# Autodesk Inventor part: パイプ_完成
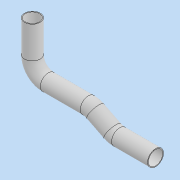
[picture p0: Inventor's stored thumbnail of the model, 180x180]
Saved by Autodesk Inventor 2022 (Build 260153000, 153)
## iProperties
Created: 2021-07
Part Number: パイプ_完成
Material: 一般
Document SubType Name: Modeling
Designer: DesignLab
Density: 1 g/cm^3
Appearance: 既定
Author: DesignLab
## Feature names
1. スイープ1
2. シェル1
## Parameters: d2 = 75 mm, d4 = 15 mm, d5 = 155 mm, d7 = 0, d8 = 0, d9 = 1 mm
